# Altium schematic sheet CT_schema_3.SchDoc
size 395 x 205 mm
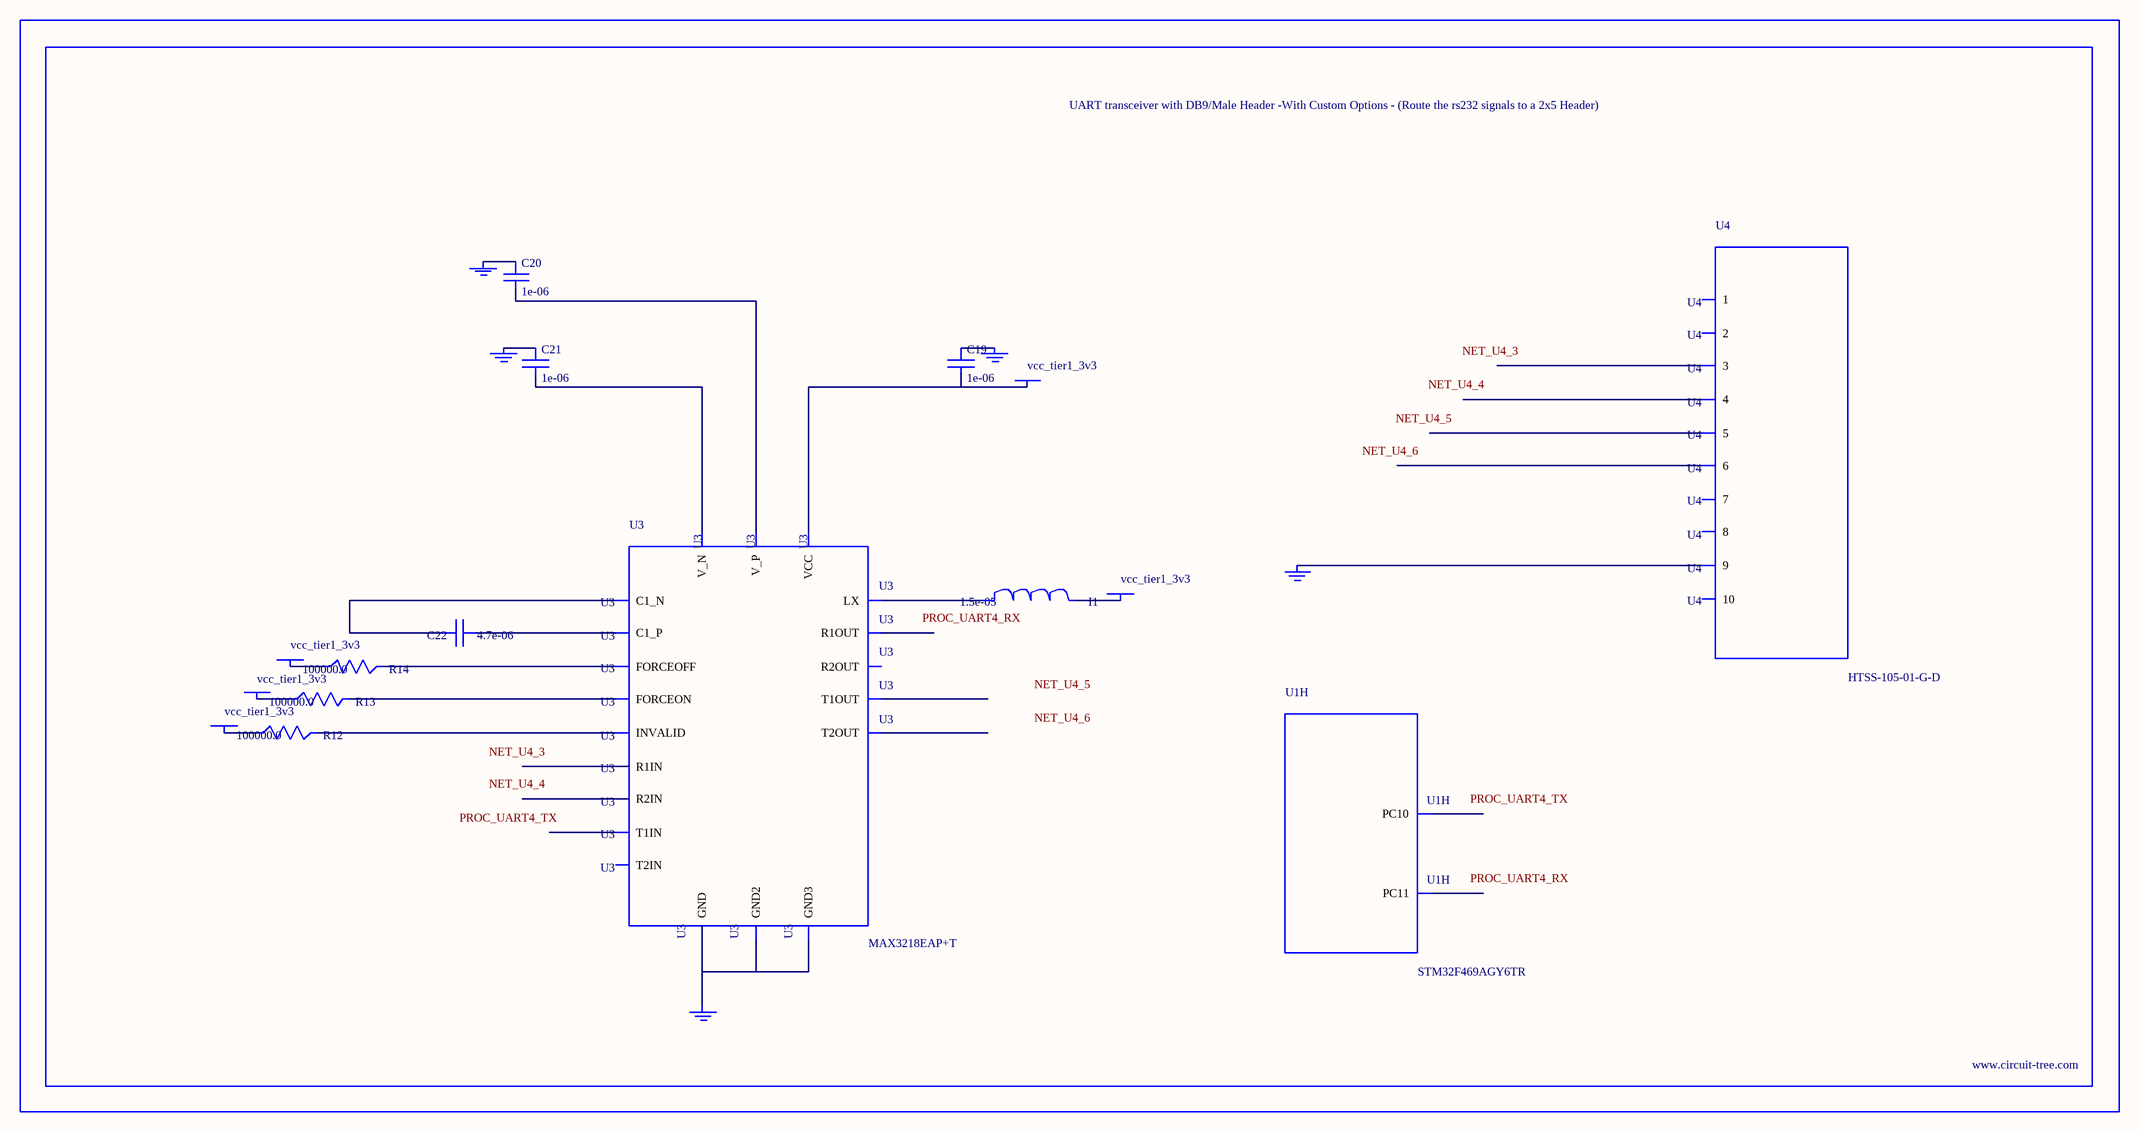
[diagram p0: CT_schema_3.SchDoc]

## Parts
BORDER2  (no value)
C19  1e-06  [C0603]
C20  1e-06  [C0603]
C21  1e-06  [C0603]
C22  4.7e-06  [C0805]
GND_INSTANCE_2_0  (no value)
GND_INSTANCE_2_1  (no value)
GND_INSTANCE_2_2  (no value)
GND_INSTANCE_2_3  (no value)
GND_INSTANCE_2_4  (no value)
I1  1.5e-05  [L1210]
POWER_INSTANCE_2_0  vcc_tier1_3v3
POWER_INSTANCE_2_1  vcc_tier1_3v3
POWER_INSTANCE_2_2  vcc_tier1_3v3
POWER_INSTANCE_2_3  vcc_tier1_3v3
POWER_INSTANCE_2_4  vcc_tier1_3v3
R12  100000.0  [R0603]
R13  100000.0  [R0603]
R14  100000.0  [R0603]
U1  STM32F469AGY6TR  [WLCSP168]  (part H of 13)
U3  MAX3218EAP+T  [SSOP-20]
U4  HTSS-105-01-G-D  [HTSS-105-01-G-D]

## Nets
NetC19_1: C19.1 GND_INSTANCE_2_0.0(GND)
NetC19_2: C19.2 POWER_INSTANCE_2_4.0(PWR) U3.6(VCC)
NetC20_1: C20.1 GND_INSTANCE_2_2.0(GND)
NetC20_2: C20.2 U3.19(V_P)
NetC21_1: C21.1 GND_INSTANCE_2_1.0(GND)
NetC21_2: C21.2 U3.15(V_N)
NetC22_1: C22.1 U3.18(C1_P)
NetC22_2: C22.2 U3.16(C1_N)
NetGND_INSTANCE_2_3_0: GND_INSTANCE_2_3.0(GND) U3.5(GND) U3.17(GND2) U3.20(GND3)
NetGND_INSTANCE_2_4_0: GND_INSTANCE_2_4.0(GND) U4.9
NetI1_1: I1.1 U3.1(LX)
NetI1_2: I1.2 POWER_INSTANCE_2_0.0(PWR)
NetPOWER_INSTANCE_2_1_0: POWER_INSTANCE_2_1.0(PWR) R12.1
NetPOWER_INSTANCE_2_2_0: POWER_INSTANCE_2_2.0(PWR) R13.1
NetPOWER_INSTANCE_2_3_0: POWER_INSTANCE_2_3.0(PWR) R14.1
NetR12_2: R12.2 U3.2(INVALID)
NetR13_2: R13.2 U3.3(FORCEON)
NetR14_2: R14.2 U3.4(FORCEOFF)

Not connected (* = marked no-connect by the designer): U1 B3(PC11) D5(PC10); U3 7(T1IN) 8(T2IN) 9(R1OUT) 10(R2OUT) 11(R2IN) 12(R1IN) 13(T2OUT) 14(T1OUT); U4 1 2 3 4 5 6 7 8 10

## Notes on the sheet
- Labels drawn without touching a wire or pin: NET_U4_3, NET_U4_4, NET_U4_5, NET_U4_6, PROC_UART4_RX, PROC_UART4_TX

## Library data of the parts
BORDER2 = BORDER_PAGE2
C19-C21 = C0603C105K3RACTU
C22 = C0805C475K4RACTU
GND_INSTANCE_2_0-GND_INSTANCE_2_4 = GND
I1 = L1210R150MDWIT
POWER_INSTANCE_2_0-POWER_INSTANCE_2_4 = PWR
R12-R14 = RC0603JR-07100KL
